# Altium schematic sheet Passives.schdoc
size 200 x 87 mm
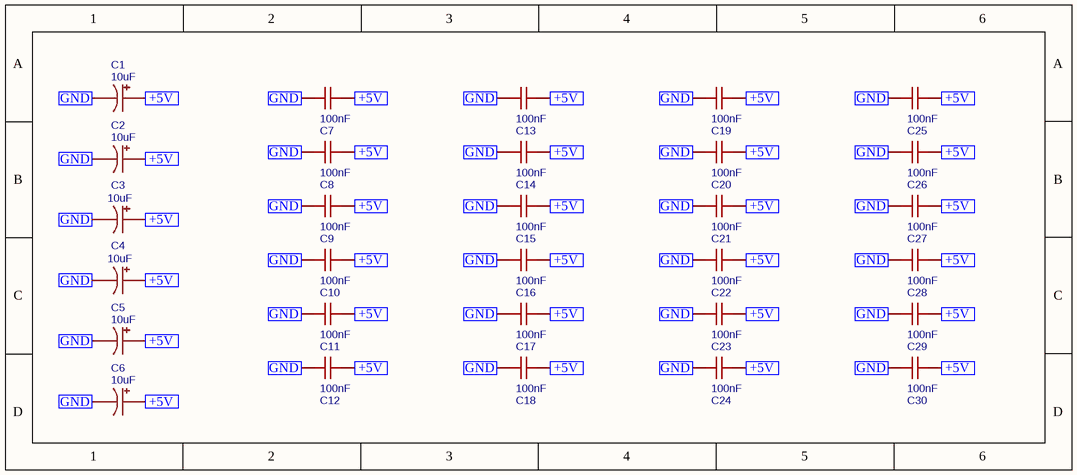
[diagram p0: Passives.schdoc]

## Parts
C1  10uF  [17MM_NARROW_AXIAL_CAP]
C2  10uF  [17MM_NARROW_AXIAL_CAP]
C3  10uF  [17MM_NARROW_AXIAL_CAP]
C4  10uF  [17MM_NARROW_AXIAL_CAP]
C5  10uF  [17MM_NARROW_AXIAL_CAP]
C6  10uF  [17MM_NARROW_AXIAL_CAP]
C7  100nF  [CERAMIC_CAP_LISA]
C8  100nF  [CERAMIC_CAP_LISA]
C9  100nF  [CERAMIC_CAP_LISA]
C10  100nF  [CERAMIC_CAP_LISA]
C11  100nF  [CERAMIC_CAP_LISA]
C12  100nF  [CERAMIC_CAP_LISA]
C13  100nF  [CERAMIC_CAP_LISA]
C14  100nF  [CERAMIC_CAP_LISA]
C15  100nF  [CERAMIC_CAP_LISA]
C16  100nF  [CERAMIC_CAP_LISA]
C17  100nF  [CERAMIC_CAP_LISA]
C18  100nF  [CERAMIC_CAP_LISA]
C19  100nF  [CERAMIC_CAP_LISA]
C20  100nF  [CERAMIC_CAP_LISA]
C21  100nF  [CERAMIC_CAP_LISA]
C22  100nF  [CERAMIC_CAP_LISA]
C23  100nF  [CERAMIC_CAP_LISA]
C24  100nF  [CERAMIC_CAP_LISA]
C25  100nF  [CERAMIC_CAP_LISA]
C26  100nF  [CERAMIC_CAP_LISA]
C27  100nF  [CERAMIC_CAP_LISA]
C28  100nF  [CERAMIC_CAP_LISA]
C29  100nF  [CERAMIC_CAP_LISA]
C30  100nF  [CERAMIC_CAP_LISA]

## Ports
+5V (in), GND (in)

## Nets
+5V: C1.1 C2.1 C3.1 C4.1 C5.1 C6.1 C7.2 C8.2 C9.2 C10.2 C11.2 C12.2 C13.2 C14.2 C15.2 C16.2 C17.2 C18.2 C19.2 C20.2 C21.2 C22.2 C23.2 C24.2 C25.2 C26.2 C27.2 C28.2 C29.2 C30.2 ; port +5V
GND: C1.2 C2.2 C3.2 C4.2 C5.2 C6.2 C7.1 C8.1 C9.1 C10.1 C11.1 C12.1 C13.1 C14.1 C15.1 C16.1 C17.1 C18.1 C19.1 C20.1 C21.1 C22.1 C23.1 C24.1 C25.1 C26.1 C27.1 C28.1 C29.1 C30.1 ; port GND

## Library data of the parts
C1-C6 = 10uF: Contributor: William Tooker
C7-C30 = 100nF: Manufacturer: TDK; Manufacturer Part: FG28X7R1H104KNT00; Contributor: LCSC; nameAlias: Capacitance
